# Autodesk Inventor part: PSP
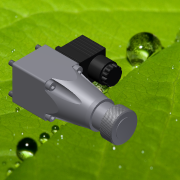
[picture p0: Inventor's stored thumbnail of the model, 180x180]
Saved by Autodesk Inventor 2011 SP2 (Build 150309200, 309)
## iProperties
Created: 2013-12
Part Number: PSP
Document SubType Name: Modeling
Designer: dorohin
Density: 1 g/cm^3
Author: dorohin
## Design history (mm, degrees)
derived "PST.iam"
node "Твердое тело1"
node "PSP_.ipt:1"
sketch "ECA_B_10.ipt:1"
sketch "Винт ГОСТ 11738-84 M 5x45:1"
sketch "Винт ГОСТ 11738-84 M 5x45:2"
sketch "Винт ГОСТ 11738-84 M 5x45:3"
sketch "Винт ГОСТ 11738-84 M 5x45:4"
